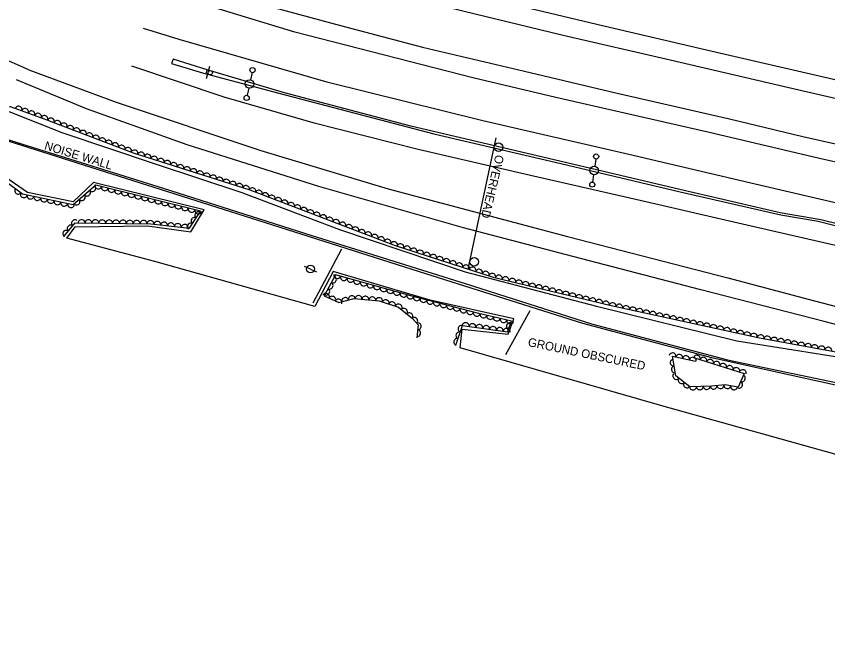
# Model space of a CAD drawing. Extents: x 1722896 to 1754269, y 648279 to 666297.
# Drawn here: x 1728856.3 to 1729327.9, y 652471.9 to 652833.2 of the extents above; entities that cross this region are included whole.
import ezdxf

# ---------------------------------------------------------------- set-up
doc = ezdxf.new("R2010")
doc.units = 0
for name, color, linetype in [('DESIGN - CENTERLINE - Proposed Text', 7, 'Continuous'), ('DESIGN - PUBLIC HEARING - Shapes', 7, 'Continuous'), ('DESIGN - SCRATCH - User 1', 7, 'Continuous'), ('SURVEY - CENTERLINE - Preliminary', 7, 'Continuous'), ('SURVEY - CENTERLINE - Preliminary Text', 7, 'Continuous'), ('SURVEY - DTM - Breaklines', 7, 'Continuous'), ('SURVEY - VEGETATION - Features with Text', 7, 'Continuous')]:
    doc.layers.add(name, color=color, linetype=linetype)

msp = doc.modelspace()

# ---------------------------------------------------------------- linework, layer by layer
at = {"layer": 'DESIGN - CENTERLINE - Proposed Text'}
for points in [[(1729028.85, 652666.66), (1729045.41, 652698.08)], [(1729028.85, 652666.66), (1729045.41, 652698.08)], [(1729140.79, 652636.66), (1729154.89, 652662.23)], [(1729140.79, 652636.66), (1729154.89, 652662.23)]]:
    msp.add_lwpolyline(points, dxfattribs=at)
at = {"layer": 'DESIGN - PUBLIC HEARING - Shapes'}
for p, q in [((1728966.8, 652797.02), (1728968.78, 652804.25)), ((1729118.89, 652686.11), (1729135.12, 652762.51)), ((1729136.53, 652757.1), (1729136.53, 652757.1)), ((1729122.37, 652690.48), (1729122.37, 652690.48))]:
    msp.add_line(p, q, dxfattribs=at)
for centre, radius in [((1728968.98, 652800.33), 1.25), ((1729136.53, 652757.12), 2.5), ((1729122.37, 652690.5), 2.5)]:
    msp.add_circle(centre, radius, dxfattribs=at)
at = {"layer": 'DESIGN - SCRATCH - User 1'}
for points in [[(1728966.62, 652799.75), (1728967.13, 652802.09), (1728947.51, 652808.22), (1728946.52, 652805.66), (1728966.4, 652799.66)], [(1730260.5, 652481.12), (1730200.23, 652500.38), (1730128.84, 652522.38), (1730050.34, 652543.58), (1729975.77, 652562.21), (1729903.48, 652579.22), (1729810.16, 652600.96), (1729713.26, 652623.18), (1729589.34, 652652.13), (1729504.2, 652671.83), (1729418.48, 652691.69), (1729323.79, 652714.91), (1729300.24, 652718.9), (1729241.89, 652732.44), (1729159, 652752.12), (1729085.49, 652769.36), (1729012.25, 652788.71), (1728967.13, 652802.09)], [(1728966.62, 652799.75), (1729008.96, 652788.47), (1729098.92, 652764.82), (1729172.8, 652747.59), (1729242.18, 652731.21), (1729300.67, 652717.74), (1729322.32, 652714.08), (1729353.29, 652706.05)], [(1729335.94, 652618.05), (1729261.31, 652634.49), (1729185.58, 652654.64), (1729086.38, 652685.99), (1729005.36, 652711.76), (1728826.88, 652768.26)], [(1728827.6, 652768.9), (1728941.57, 652733.27), (1729028.01, 652705.76), (1729117.07, 652677.76), (1729190.6, 652654.49), (1729269.65, 652633.51), (1729341.85, 652618.3)]]:
    msp.add_lwpolyline(points, dxfattribs=at)
at = {"layer": 'SURVEY - CENTERLINE - Preliminary'}
for points in [[(1728839.21, 652782.87), (1728882.71, 652765.63), (1728936.98, 652747.35), (1728987.45, 652730.66), (1729044.2, 652709.33), (1729117.23, 652684.56), (1729193.58, 652664.65), (1729275.03, 652644.58), (1729353.04, 652632.13)], [(1729345.24, 652575.02), (1729231.46, 652606.78), (1729114.2, 652640.4), (1729115.49, 652651.26), (1729142.24, 652648.49), (1729145.36, 652657.33), (1729096.9, 652668.13), (1729040.43, 652684.85), (1729029.85, 652664.42), (1728936.79, 652690.7), (1728885.73, 652704.16), (1728890.59, 652710.77), (1728932.58, 652711.43), (1728957.67, 652707.94), (1728965.56, 652720.61), (1728901.1, 652736.56), (1728889.39, 652725.26), (1728862.74, 652730.68), (1728822.41, 652758.57)]]:
    msp.add_lwpolyline(points, dxfattribs=at)
at = {"layer": 'SURVEY - CENTERLINE - Preliminary Text'}
for points in [[(1728863.54, 652802.06), (1728821.49, 652820.38), (1728775.21, 652842.27), (1728720.82, 652870.99), (1728671.26, 652900.62), (1728624.08, 652930.96), (1728572.88, 652968.45), (1728532.23, 653000.37), (1728494.67, 653032.49), (1728463.45, 653061.14), (1728427.34, 653096.22), (1728393.97, 653130.25), (1728350.31, 653176.66), (1728303.78, 653227.57), (1728262.44, 653275.42), (1728217.62, 653331.31), (1728173.02, 653392.32), (1728133.95, 653450.97), (1728099.2, 653506.95), (1728072.75, 653552.44)], [(1728956.15, 652890.93), (1729010.29, 652874.92), (1729065.83, 652859.63), (1729135.05, 652842.49), (1729197.78, 652827.59), (1729263.16, 652812.24), (1729325.44, 652798.03), (1729390.09, 652782.81)], [(1728947.46, 652883.31), (1728989.83, 652869.72), (1729049.11, 652853.23), (1729115.83, 652836.33), (1729174.03, 652822.25), (1729236.28, 652807.87), (1729305.3, 652791.72), (1729368.24, 652777.24)], [(1728927.75, 652862.44), (1728951.61, 652854.51), (1728996.67, 652840.87), (1729041.76, 652828.53), (1729092.31, 652815.24), (1729151.73, 652801.37), (1729205.56, 652788.57), (1729270.79, 652773.64), (1729313.44, 652763.39), (1729359.16, 652752.98)], [(1730270.3, 652515.2), (1730228.96, 652529.12), (1730166.13, 652549.21), (1730105.7, 652566.49), (1730051.45, 652580.8), (1730001.69, 652593.2), (1729955.68, 652604.21), (1729906, 652615.94), (1729848.69, 652629.12), (1729783.93, 652644.03), (1729726.92, 652657.34), (1729658.34, 652673.01), (1729604.33, 652685.78), (1729534.44, 652701.71), (1729459.5, 652718.9), (1729384.48, 652736.76), (1729323.16, 652750.51), (1729258.16, 652765.72), (1729169.76, 652786), (1729121.61, 652797.37), (1729018.16, 652823.93), (1728918.71, 652854.37)], [(1730264.12, 652492.62), (1730202.7, 652513.21), (1730154.17, 652528.69), (1730110.08, 652541.21), (1730056.32, 652555.48), (1729990.67, 652572.07), (1729928.6, 652586.81), (1729860.63, 652602.43), (1729797.44, 652617.47), (1729715.52, 652636.12), (1729640.3, 652653.56), (1729569.25, 652670.14), (1729500.79, 652685.57), (1729431.64, 652701.97), (1729354.64, 652719.58), (1729285.63, 652735.52), (1729212.27, 652752.8), (1729127.4, 652772.45), (1729037.59, 652794.76), (1728950.93, 652819.74), (1728930.15, 652826.14)], [(1728863.54, 652802.06), (1728914.24, 652783.32), (1728998.46, 652755.12), (1729072.36, 652732.97), (1729176.61, 652705.26), (1729269.73, 652681.15), (1729320.24, 652667.83), (1729376.75, 652653.05)], [(1728923.18, 652804.43), (1728976.92, 652786.42), (1729028.71, 652771.38), (1729089.83, 652756), (1729155.11, 652740.87), (1729217.1, 652726.75), (1729283.33, 652711.33), (1729334.81, 652699.48), (1729422.85, 652679.58), (1729666.73, 652624.57), (1729724.92, 652611.43), (1729788.41, 652596.68), (1729859.59, 652580.32), (1729938.86, 652561.99), (1730018.53, 652542.72), (1730091.86, 652523.7), (1730150.75, 652506.89), (1730199.99, 652491.57), (1730225.61, 652483.06), (1730258.51, 652471.91)], [(1729416.14, 652632.29), (1729325.7, 652655.79), (1729254.04, 652674.09), (1729179.77, 652693.45), (1729116.15, 652710.14), (1729032.17, 652734.29), (1728955.6, 652758.39), (1728897.07, 652779.35), (1728856.38, 652796.27)]]:
    msp.add_lwpolyline(points, dxfattribs=at)
at = {"layer": 'SURVEY - DTM - Breaklines'}
for p, q in [((1728993.3, 652800.43), (1728992.41, 652796.27)), ((1728991.36, 652791.38), (1728990.47, 652787.23)), ((1729193.08, 652750.18), (1729192.5, 652745.97)), ((1729191.82, 652741.02), (1729191.24, 652736.81)), ((1729027.26, 652686.24), (1729023.83, 652687.76)), ((1729027.26, 652686.24), (1729030.68, 652684.72))]:
    msp.add_line(p, q, dxfattribs=at)
for centre, radius in [((1728993.61, 652801.89), 1.5), ((1728991.88, 652793.83), 2.5), ((1728990.15, 652785.76), 1.5), ((1729193.28, 652751.67), 1.5), ((1729192.16, 652743.5), 2.5), ((1729191.03, 652735.33), 1.5), ((1729027.26, 652686.24), 2.25)]:
    msp.add_circle(centre, radius, dxfattribs=at)
at = {"layer": 'SURVEY - VEGETATION - Features with Text'}
for points in [[(1728832.56, 652782.44), (1728839.2, 652779.68), (1728852.72, 652780.77), (1728873.99, 652773.07), (1728924.17, 652753.81), (1728991.95, 652732.2), (1729076.45, 652700.03), (1729133.5, 652681.62), (1729201.94, 652664.99), (1729288.27, 652646.21), (1729365.53, 652632.1)], [(1728883.99, 652705.25), (1728890.51, 652713.16), (1728934.54, 652712.53), (1728956.9, 652709.99), (1728963.44, 652719.82), (1728902.6, 652734.94), (1728889.27, 652723.63), (1728859.89, 652729.82), (1728820.14, 652759.29), (1728822.47, 652769.13)], [(1729111.83, 652641.96), (1729115.56, 652653.43), (1729141.82, 652649.8), (1729144.15, 652656), (1729124.39, 652660.56), (1729085.67, 652670.63), (1729041.89, 652682.81), (1729035.2, 652670.65), (1729043.8, 652666.78), (1729052.63, 652669.21), (1729067.2, 652667.73), (1729078.4, 652664.04), (1729086.48, 652657.42), (1729089.81, 652653.85), (1729089.09, 652646.23)], [(1729249.95, 652634.86), (1729279.32, 652625.6), (1729275.84, 652617.55), (1729268.19, 652618.87), (1729260.29, 652618.26), (1729247.74, 652617.75), (1729239.56, 652624.15), (1729237.59, 652635.66), (1729250.93, 652632.77)]]:
    msp.add_lwpolyline(points, dxfattribs=at)
for centre, major_axis in [((1728857.66, 652778.98), (1.88, -0.68)), ((1728861.42, 652777.62), (1.88, -0.68)), ((1728865.18, 652776.26), (1.88, -0.68)), ((1728868.94, 652774.9), (1.88, -0.68)), ((1728872.7, 652773.54), (1.88, -0.68)), ((1728876.44, 652772.13), (1.87, -0.72)), ((1728880.18, 652770.7), (1.87, -0.72)), ((1728883.91, 652769.26), (1.87, -0.72)), ((1728887.65, 652767.83), (1.87, -0.72)), ((1728891.38, 652766.4), (1.87, -0.72)), ((1728895.12, 652764.96), (1.87, -0.72)), ((1728898.85, 652763.53), (1.87, -0.72)), ((1728902.58, 652762.1), (1.87, -0.72)), ((1728906.32, 652760.66), (1.87, -0.72)), ((1728910.05, 652759.23), (1.87, -0.72)), ((1728913.79, 652757.8), (1.87, -0.72)), ((1728917.52, 652756.36), (1.87, -0.72)), ((1728921.26, 652754.93), (1.87, -0.72)), ((1728925.01, 652753.54), (1.91, -0.61)), ((1728928.82, 652752.33), (1.91, -0.61)), ((1728932.63, 652751.11), (1.91, -0.61)), ((1728936.44, 652749.9), (1.91, -0.61)), ((1728940.25, 652748.68), (1.91, -0.61)), ((1728944.06, 652747.47), (1.91, -0.61)), ((1728947.87, 652746.25), (1.91, -0.61)), ((1728951.68, 652745.04), (1.91, -0.61)), ((1728955.5, 652743.82), (1.91, -0.61)), ((1728959.31, 652742.61), (1.91, -0.61)), ((1728963.12, 652741.39), (1.91, -0.61)), ((1728966.93, 652740.18), (1.91, -0.61)), ((1728970.74, 652738.96), (1.91, -0.61)), ((1728974.55, 652737.75), (1.91, -0.61)), ((1728978.36, 652736.53), (1.91, -0.61)), ((1728900.53, 652733.19), (-1.52, -1.29)), ((1728903.85, 652734.63), (-1.94, 0.48)), ((1728907.73, 652733.67), (-1.94, 0.48)), ((1728982.17, 652735.31), (1.91, -0.61)), ((1728985.98, 652734.1), (1.91, -0.61)), ((1728989.79, 652732.88), (1.91, -0.61)), ((1728857.32, 652731.72), (-1.61, 1.19)), ((1728860.67, 652729.65), (-1.96, 0.41)), ((1728864.58, 652728.83), (-1.96, 0.41)), ((1728894.43, 652728.01), (-1.52, -1.29)), ((1728897.48, 652730.6), (-1.52, -1.29)), ((1728911.61, 652732.7), (-1.94, 0.48)), ((1728915.49, 652731.74), (-1.94, 0.48)), ((1728919.38, 652730.77), (-1.94, 0.48)), ((1728923.26, 652729.81), (-1.94, 0.48)), ((1728927.14, 652728.84), (-1.94, 0.48)), ((1728993.57, 652731.58), (1.87, -0.71)), ((1728997.31, 652730.16), (1.87, -0.71)), ((1729001.05, 652728.73), (1.87, -0.71)), ((1729004.79, 652727.31), (1.87, -0.71)), ((1728868.5, 652728), (-1.96, 0.41)), ((1728872.41, 652727.18), (-1.96, 0.41)), ((1728876.33, 652726.35), (-1.96, 0.41)), ((1728880.24, 652725.53), (-1.96, 0.41)), ((1728884.15, 652724.71), (-1.96, 0.41)), ((1728891.38, 652725.42), (-1.52, -1.29)), ((1728931.02, 652727.88), (-1.94, 0.48)), ((1728934.9, 652726.91), (-1.94, 0.48)), ((1728938.79, 652725.95), (-1.94, 0.48)), ((1728942.67, 652724.98), (-1.94, 0.48)), ((1728946.55, 652724.02), (-1.94, 0.48)), ((1729008.53, 652725.89), (1.87, -0.71)), ((1729012.26, 652724.46), (1.87, -0.71)), ((1729016, 652723.04), (1.87, -0.71)), ((1728888.07, 652723.88), (-1.96, 0.41)), ((1728950.43, 652723.06), (-1.94, 0.48)), ((1728954.31, 652722.09), (-1.94, 0.48)), ((1728958.2, 652721.13), (-1.94, 0.48)), ((1728962, 652717.66), (1.11, 1.66)), ((1728962.08, 652720.16), (-1.94, 0.48)), ((1729019.74, 652721.62), (1.87, -0.71)), ((1729023.48, 652720.19), (1.87, -0.71)), ((1729027.22, 652718.77), (1.87, -0.71)), ((1728890.35, 652712.96), (1.27, 1.54)), ((1728894.26, 652713.1), (2, -0.03)), ((1728898.26, 652713.05), (2, -0.03)), ((1728959.79, 652714.33), (1.11, 1.66)), ((1729030.96, 652717.35), (1.87, -0.71)), ((1729034.69, 652715.92), (1.87, -0.71)), ((1729038.43, 652714.5), (1.87, -0.71)), ((1729042.17, 652713.08), (1.87, -0.71)), ((1728887.81, 652709.88), (1.27, 1.54)), ((1728902.26, 652712.99), (2, -0.03)), ((1728906.26, 652712.93), (2, -0.03)), ((1728910.26, 652712.88), (2, -0.03)), ((1728914.26, 652712.82), (2, -0.03)), ((1728918.26, 652712.76), (2, -0.03)), ((1728922.26, 652712.71), (2, -0.03)), ((1728926.26, 652712.65), (2, -0.03)), ((1728930.26, 652712.59), (2, -0.03)), ((1728934.26, 652712.54), (2, -0.03)), ((1728938.23, 652712.11), (1.99, -0.23)), ((1728942.21, 652711.66), (1.99, -0.23)), ((1728946.18, 652711.21), (1.99, -0.23)), ((1728950.16, 652710.76), (1.99, -0.23)), ((1728954.13, 652710.3), (1.99, -0.23)), ((1728957.57, 652711), (1.11, 1.66)), ((1729045.91, 652711.65), (1.87, -0.71)), ((1729049.65, 652710.23), (1.87, -0.71)), ((1729053.39, 652708.81), (1.87, -0.71)), ((1728885.27, 652706.79), (1.27, 1.54)), ((1729057.12, 652707.38), (1.87, -0.71)), ((1729060.86, 652705.96), (1.87, -0.71)), ((1729064.6, 652704.54), (1.87, -0.71)), ((1729068.34, 652703.12), (1.87, -0.71)), ((1729072.08, 652701.69), (1.87, -0.71)), ((1729075.81, 652700.27), (1.87, -0.71)), ((1729079.61, 652699.01), (1.9, -0.61)), ((1729083.42, 652697.78), (1.9, -0.61)), ((1729087.22, 652696.55), (1.9, -0.61)), ((1729091.03, 652695.32), (1.9, -0.61)), ((1729094.84, 652694.09), (1.9, -0.61)), ((1729098.64, 652692.87), (1.9, -0.61)), ((1729102.45, 652691.64), (1.9, -0.61)), ((1729106.26, 652690.41), (1.9, -0.61)), ((1729110.06, 652689.18), (1.9, -0.61)), ((1729113.87, 652687.95), (1.9, -0.61)), ((1729117.68, 652686.72), (1.9, -0.61)), ((1729121.48, 652685.5), (1.9, -0.61)), ((1729042.78, 652682.56), (-1.93, 0.54)), ((1729046.63, 652681.49), (-1.93, 0.54)), ((1729125.29, 652684.27), (1.9, -0.61)), ((1729129.1, 652683.04), (1.9, -0.61)), ((1729132.9, 652681.81), (1.9, -0.61)), ((1729136.78, 652680.82), (1.94, -0.47)), ((1729140.67, 652679.88), (1.94, -0.47)), ((1729038.48, 652676.61), (-0.96, -1.75)), ((1729040.41, 652680.11), (-0.96, -1.75)), ((1729050.49, 652680.42), (-1.93, 0.54)), ((1729054.34, 652679.34), (-1.93, 0.54)), ((1729058.2, 652678.27), (-1.93, 0.54)), ((1729062.05, 652677.2), (-1.93, 0.54)), ((1729144.55, 652678.93), (1.94, -0.47)), ((1729148.44, 652677.99), (1.94, -0.47)), ((1729152.33, 652677.05), (1.94, -0.47)), ((1729156.21, 652676.1), (1.94, -0.47)), ((1729160.1, 652675.16), (1.94, -0.47)), ((1729036.55, 652673.1), (-0.96, -1.75)), ((1729065.9, 652676.13), (-1.93, 0.54)), ((1729069.76, 652675.05), (-1.93, 0.54)), ((1729073.61, 652673.98), (-1.93, 0.54)), ((1729077.46, 652672.91), (-1.93, 0.54)), ((1729163.99, 652674.21), (1.94, -0.47)), ((1729167.87, 652673.27), (1.94, -0.47)), ((1729171.76, 652672.33), (1.94, -0.47)), ((1729175.65, 652671.38), (1.94, -0.47)), ((1729179.54, 652670.44), (1.94, -0.47)), ((1729036.29, 652670.16), (1.82, -0.82)), ((1729039.94, 652668.52), (1.82, -0.82)), ((1729043.59, 652666.88), (1.82, -0.82)), ((1729047.43, 652667.78), (1.93, 0.53)), ((1729051.29, 652668.84), (1.93, 0.53)), ((1729055.22, 652668.95), (1.99, -0.2)), ((1729059.2, 652668.55), (1.99, -0.2)), ((1729063.18, 652668.14), (1.99, -0.2)), ((1729067.16, 652667.74), (1.99, -0.2)), ((1729070.96, 652666.49), (1.9, -0.63)), ((1729081.32, 652671.84), (-1.93, 0.54)), ((1729085.17, 652670.76), (-1.93, 0.54)), ((1729089.04, 652669.75), (-1.94, 0.5)), ((1729092.91, 652668.74), (-1.94, 0.5)), ((1729096.78, 652667.74), (-1.94, 0.5)), ((1729183.42, 652669.49), (1.94, -0.47)), ((1729187.31, 652668.55), (1.94, -0.47)), ((1729191.2, 652667.6), (1.94, -0.47)), ((1729195.08, 652666.66), (1.94, -0.47)), ((1729198.97, 652665.72), (1.94, -0.47)), ((1729074.76, 652665.24), (1.9, -0.63)), ((1729078.53, 652663.93), (1.55, -1.27)), ((1729081.63, 652661.4), (1.55, -1.27)), ((1729100.65, 652666.73), (-1.94, 0.5)), ((1729104.52, 652665.72), (-1.94, 0.5)), ((1729108.4, 652664.72), (-1.94, 0.5)), ((1729112.27, 652663.71), (-1.94, 0.5)), ((1729116.14, 652662.7), (-1.94, 0.5)), ((1729202.86, 652664.79), (1.95, -0.43)), ((1729206.77, 652663.94), (1.95, -0.43)), ((1729210.68, 652663.09), (1.95, -0.43)), ((1729214.59, 652662.24), (1.95, -0.43)), ((1729218.5, 652661.39), (1.95, -0.43)), ((1729084.72, 652658.86), (1.55, -1.27)), ((1729087.66, 652656.16), (1.36, -1.46)), ((1729120.01, 652661.7), (-1.94, 0.5)), ((1729123.88, 652660.69), (-1.94, 0.5)), ((1729127.78, 652659.78), (-1.95, 0.45)), ((1729131.67, 652658.88), (-1.95, 0.45)), ((1729135.57, 652657.98), (-1.95, 0.45)), ((1729222.4, 652660.54), (1.95, -0.43)), ((1729226.31, 652659.69), (1.95, -0.43)), ((1729230.22, 652658.84), (1.95, -0.43)), ((1729234.13, 652657.99), (1.95, -0.43)), ((1729238.04, 652657.14), (1.95, -0.43)), ((1729241.95, 652656.29), (1.95, -0.43)), ((1729089.73, 652653.01), (-0.19, -1.99)), ((1729114.93, 652651.47), (0.62, 1.9)), ((1729117.48, 652653.17), (1.98, -0.27)), ((1729121.44, 652652.62), (1.98, -0.27)), ((1729125.41, 652652.07), (1.98, -0.27)), ((1729139.47, 652657.08), (-1.95, 0.45)), ((1729143.03, 652653.01), (0.7, 1.87)), ((1729143.37, 652656.18), (-1.95, 0.45)), ((1729245.86, 652655.44), (1.95, -0.43)), ((1729249.76, 652654.59), (1.95, -0.43)), ((1729253.67, 652653.74), (1.95, -0.43)), ((1729257.58, 652652.89), (1.95, -0.43)), ((1729261.49, 652652.04), (1.95, -0.43)), ((1729089.36, 652649.03), (-0.19, -1.99)), ((1729113.69, 652647.67), (0.62, 1.9)), ((1729129.37, 652651.52), (1.98, -0.27)), ((1729133.33, 652650.97), (1.98, -0.27)), ((1729137.29, 652650.43), (1.98, -0.27)), ((1729141.26, 652649.88), (1.98, -0.27)), ((1729265.4, 652651.19), (1.95, -0.43)), ((1729269.31, 652650.34), (1.95, -0.43)), ((1729273.22, 652649.49), (1.95, -0.43)), ((1729277.12, 652648.63), (1.95, -0.43)), ((1729281.03, 652647.78), (1.95, -0.43)), ((1729284.94, 652646.93), (1.95, -0.43)), ((1729112.45, 652643.86), (0.62, 1.9)), ((1729288.85, 652646.1), (1.97, -0.36)), ((1729292.79, 652645.38), (1.97, -0.36)), ((1729296.72, 652644.67), (1.97, -0.36)), ((1729300.66, 652643.95), (1.97, -0.36)), ((1729304.59, 652643.23), (1.97, -0.36)), ((1729308.53, 652642.51), (1.97, -0.36)), ((1729312.46, 652641.79), (1.97, -0.36)), ((1729316.4, 652641.07), (1.97, -0.36)), ((1729320.33, 652640.35), (1.97, -0.36)), ((1729324.27, 652639.63), (1.97, -0.36)), ((1729328.2, 652638.92), (1.97, -0.36)), ((1729237.7, 652635.64), (1.95, -0.42)), ((1729241.61, 652634.79), (1.95, -0.42)), ((1729245.52, 652633.94), (1.95, -0.42)), ((1729249.43, 652633.09), (1.95, -0.42)), ((1729251.86, 652634.26), (1.91, -0.6)), ((1729255.67, 652633.05), (1.91, -0.6)), ((1729238.24, 652631.83), (-0.34, 1.97)), ((1729259.49, 652631.85), (1.91, -0.6)), ((1729263.3, 652630.65), (1.91, -0.6)), ((1729267.12, 652629.45), (1.91, -0.6)), ((1729270.93, 652628.24), (1.91, -0.6)), ((1729238.92, 652627.89), (-0.34, 1.97)), ((1729274.75, 652627.04), (1.91, -0.6)), ((1729278.56, 652625.84), (1.91, -0.6)), ((1729239.73, 652624.03), (-1.57, 1.23)), ((1729242.88, 652621.56), (-1.57, 1.23)), ((1729276.47, 652618.99), (-0.79, -1.84)), ((1729278.05, 652622.66), (-0.79, -1.84)), ((1729246.02, 652619.09), (-1.57, 1.23)), ((1729249.56, 652617.82), (-2, -0.08)), ((1729253.56, 652617.98), (-2, -0.08)), ((1729257.55, 652618.14), (-2, -0.08)), ((1729261.55, 652618.35), (-1.99, -0.16)), ((1729265.53, 652618.66), (-1.99, -0.16)), ((1729269.51, 652618.64), (-1.97, 0.34)), ((1729273.45, 652617.96), (-1.97, 0.34))]:
    msp.add_ellipse(centre, major_axis=major_axis, ratio=0.940188, start_param=0, end_param=3.141593, dxfattribs=at)

# ---------------------------------------------------------------- texts
at = {"layer": 'DESIGN - PUBLIC HEARING - Shapes'}
msp.add_text('OVERHEAD', height=5, rotation=256.7804, dxfattribs=at).set_placement((1729134.91, 652752.99))
at = {"layer": 'DESIGN - SCRATCH - User 1'}
msp.add_text('NOISE WALL', height=5, rotation=342.9071, dxfattribs=at).set_placement((1728872.23, 652755.94))
at = {"layer": 'SURVEY - CENTERLINE - Preliminary'}
msp.add_text('GROUND OBSCURED', height=5, rotation=348.2399, dxfattribs=at).set_placement((1729153.3, 652641.54))

doc.saveas('drawing.dxf')
